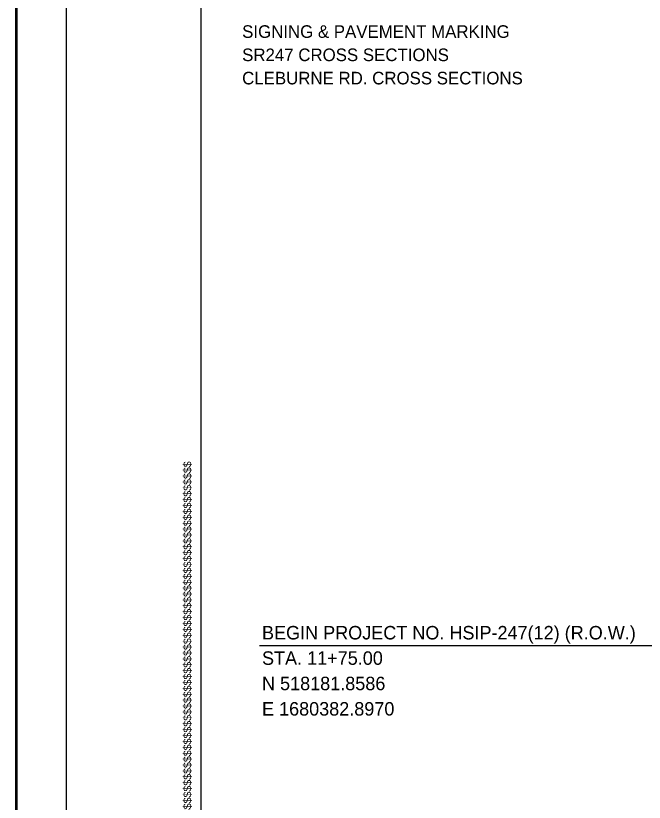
# Model space of a CAD drawing. Extents: x 1577619 to 1828281, y 483481 to 598136.
# Drawn here: x 1647461 to 1663305, y 507802 to 527639 of the extents above; entities that cross this region are included whole.
import ezdxf

# ---------------------------------------------------------------- set-up
doc = ezdxf.new("R2010")
doc.units = 0
for name, color, linetype in [('DESIGN - CENTERLINE - Proposed Text', 7, 'Continuous'), ('DESIGN - SHEET - Corner Text', 7, 'Continuous'), ('DESIGN - SHEET - Linework', 7, 'Continuous'), ('DESIGN - SHEET - Plot Shape', 7, 'Continuous')]:
    doc.layers.add(name, color=color, linetype=linetype)

msp = doc.modelspace()

# ---------------------------------------------------------------- linework, layer by layer
at = {"layer": 'DESIGN - CENTERLINE - Proposed Text'}
msp.add_lwpolyline([(1680381, 518131), (1666391, 511746), (1653607, 511746)], dxfattribs=at)
at = {"layer": 'DESIGN - SHEET - Linework'}
msp.add_line((1647461, 496549), (1647461, 540205), dxfattribs=at)
msp.add_lwpolyline([(1652139, 539377), (1715107, 539377), (1715107, 497377), (1652139, 497377), (1652139, 539377)], dxfattribs=at)
at = {"layer": 'DESIGN - SHEET - Plot Shape'}
for points in [[(1647501, 540165), (1715501, 540165), (1715501, 496589), (1647501, 496589)], [(1648737, 539377), (1715107, 539377), (1715107, 497377), (1648737, 497377)]]:
    msp.add_lwpolyline(points, close=True, dxfattribs=at)

# ---------------------------------------------------------------- texts
at = {"layer": 'DESIGN - CENTERLINE - Proposed Text'}
for s, p in [('BEGIN PROJECT NO. HSIP-247(12) (R.O.W.)', (1653669, 511908)), ('STA. 11+75.00 ', (1653669, 511268)), ('N 518181.8586', (1653669, 510628)), ('E 1680382.8970', (1653669, 509988))]:
    msp.add_text(s, height=340, dxfattribs=at).set_placement(p)
at = {"layer": 'DESIGN - SHEET - Corner Text'}
for s, p in [('SIGNING & PAVEMENT MARKING', (1653168, 527081)), ('SR247 CROSS SECTIONS', (1653168, 526494)), ('CLEBURNE RD. CROSS SECTIONS', (1653168, 525907))]:
    msp.add_text(s, height=317.43, dxfattribs=at).set_placement(p)
msp.add_text('$$$$DGNSPEC$$$$$$$$$$$$$$$$$$$$$$$$$$$$$$$$$$$$$$$$$$$$$$$$$$$$$$$$$$$$$$$$$$$$$$$$$$$$$$$$$$$$$$$$$$$$$$$$$$$$$$$$$$$$$$$$$$$', height=200.004, rotation=90, dxfattribs=at).set_placement((1651887, 497377))

doc.saveas('drawing.dxf')
